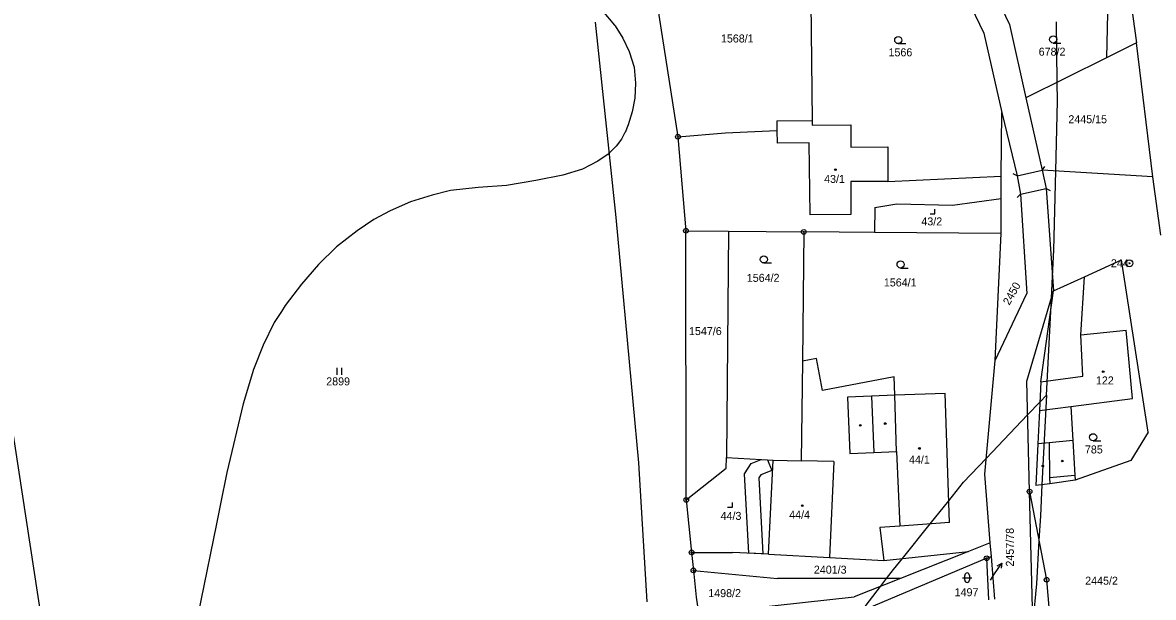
# Model space of a CAD drawing. Extents: x -546762 to -540209, y -1046851 to -1035694.
# Drawn here: x -542845.1 to -542604.8, y -1039792.3 to -1039670.1 of the extents above; entities that cross this region are included whole.
import ezdxf

# ---------------------------------------------------------------- set-up
doc = ezdxf.new("R2010")
doc.units = 0
for name, color, linetype in [('Vrstva 1', 7, 'Continuous'), ('Vrstva 16', 7, 'Continuous'), ('Vrstva 17', 7, 'Continuous'), ('Vrstva 18', 7, 'Continuous'), ('Vrstva 19', 7, 'Continuous'), ('Vrstva 24', 7, 'Continuous'), ('Vrstva 25', 7, 'Continuous'), ('Vrstva 26', 7, 'Continuous'), ('Vrstva 3', 7, 'Continuous'), ('Vrstva 30', 7, 'Continuous'), ('Vrstva 37', 7, 'Continuous'), ('Vrstva 4', 7, 'Continuous'), ('Vrstva 52', 7, 'Continuous')]:
    doc.layers.add(name, color=color, linetype=linetype)

msp = doc.modelspace()

# ---------------------------------------------------------------- linework, layer by layer
at = {"layer": 'Vrstva 1'}
for p, q in [((-542705.86, -1039694.34), (-542695.7, -1039693.46)), ((-542695.1, -1039714.41), (-542679.1, -1039714.55)), ((-542679.1, -1039714.55), (-542679.4, -1039742.03)), ((-542664.09, -1039714.68), (-542679.1, -1039714.55)), ((-542676.41, -1039741.47), (-542679.4, -1039742.03)), ((-542679.4, -1039742.03), (-542679.64, -1039763.24)), ((-542631.14, -1039769.78), (-542631.73, -1039746.29)), ((-542695.54, -1039762.52), (-542685.64, -1039763.13)), ((-542686.57, -1039783.12), (-542685.64, -1039763.13)), ((-542685.64, -1039763.13), (-542679.64, -1039763.24)), ((-542672.75, -1039763.36), (-542679.64, -1039763.24)), ((-542672.75, -1039763.36), (-542673.67, -1039783.8)), ((-542704.09, -1039771.57), (-542695.56, -1039764.83)), ((-542630.45, -1039797.36), (-542631.14, -1039769.78)), ((-542631.14, -1039769.78), (-542627.51, -1039788.55)), ((-542702.94, -1039782.71), (-542694.24, -1039782.72)), ((-542640.24, -1039783.98), (-542668.91, -1039796.07)), ((-542640.24, -1039783.98), (-542639.24, -1039783.56)), ((-542639.75, -1039792.83), (-542640.24, -1039783.98)), ((-542702.54, -1039786.55), (-542684.72, -1039788.3)), ((-542627.51, -1039788.55), (-542625.49, -1039812.67))]:
    msp.add_line(p, q, dxfattribs=at)
for points in [[(-542712.36, -1039652.51), (-542705.86, -1039694.34)], [(-542677.71, -1039653), (-542677.33, -1039690.89)], [(-542611.68, -1039650.85), (-542608.44, -1039674.34)], [(-542649.92, -1039653.39), (-542640.84, -1039672.31)], [(-542614.29, -1039655.34), (-542614.78, -1039677.52)], [(-542640.62, -1039659.5), (-542635.36, -1039670.45)], [(-542860.51, -1039670.07), (-542839.48, -1039807.43)], [(-542723.46, -1039669.94), (-542719.06, -1039711.53)], [(-542635.36, -1039670.45), (-542631.89, -1039686.08)], [(-542640.84, -1039672.31), (-542636.99, -1039689.14)], [(-542608.44, -1039674.34), (-542614.78, -1039677.52)], [(-542604.91, -1039702.82), (-542608.44, -1039674.34)], [(-542614.78, -1039677.52), (-542631.89, -1039686.08)], [(-542631.89, -1039686.08), (-542628.47, -1039701.44)], [(-542684.83, -1039690.96), (-542677.33, -1039690.89)], [(-542684.83, -1039690.96), (-542684.81, -1039693)], [(-542677.33, -1039690.89), (-542677.32, -1039691.89)], [(-542637.19, -1039702.74), (-542636.99, -1039689.14)], [(-542636.99, -1039689.14), (-542633.76, -1039702.65)], [(-542695.7, -1039693.46), (-542684.81, -1039693)], [(-542677.32, -1039691.89), (-542669.12, -1039691.81)], [(-542669.12, -1039691.81), (-542669.11, -1039696.52)], [(-542705.86, -1039694.34), (-542704.14, -1039714.33)], [(-542669.11, -1039696.52), (-542661.24, -1039696.5)], [(-542661.24, -1039696.5), (-542661.22, -1039703.84)], [(-542661.22, -1039703.84), (-542637.19, -1039702.74)], [(-542637.19, -1039707.46), (-542637.19, -1039702.74)], [(-542633.76, -1039702.65), (-542633.08, -1039706.56)], [(-542604.91, -1039702.82), (-542628.47, -1039701.44)], [(-542628.47, -1039701.44), (-542627.6, -1039705.31)], [(-542603.22, -1039715.27), (-542604.91, -1039702.82)], [(-542627.6, -1039705.31), (-542626.02, -1039727.12)], [(-542647.51, -1039708.9), (-542637.19, -1039707.46)], [(-542637.19, -1039714.92), (-542637.19, -1039707.46)], [(-542633.08, -1039706.56), (-542631.68, -1039727.64)], [(-542663.99, -1039709.39), (-542664.09, -1039714.68)], [(-542663.99, -1039709.39), (-542659.3, -1039708.58)], [(-542659.3, -1039708.58), (-542647.51, -1039708.9)], [(-542719.06, -1039711.53), (-542714.22, -1039763.64)], [(-542704.14, -1039714.33), (-542695.1, -1039714.41)], [(-542704.09, -1039771.57), (-542704.14, -1039714.33)], [(-542695.1, -1039714.41), (-542695.54, -1039762.52)], [(-542637.19, -1039714.92), (-542664.09, -1039714.68)], [(-542638.46, -1039741.92), (-542637.19, -1039714.92)], [(-542619.45, -1039724.1), (-542611.58, -1039720.48)], [(-542605.96, -1039757.18), (-542611.58, -1039720.48)], [(-542626.02, -1039727.12), (-542619.45, -1039724.1)], [(-542620.2, -1039736.44), (-542619.45, -1039724.1)], [(-542631.73, -1039746.29), (-542626.02, -1039727.12)], [(-542628.7, -1039746.43), (-542626.02, -1039727.12)], [(-542638.46, -1039741.92), (-542631.68, -1039727.64)], [(-542620.2, -1039736.44), (-542610.58, -1039735.47)], [(-542609.28, -1039750.02), (-542610.58, -1039735.47)], [(-542675.14, -1039748.26), (-542676.41, -1039741.47)], [(-542640.66, -1039766.08), (-542638.46, -1039741.92)], [(-542659.91, -1039745.41), (-542675.14, -1039748.26)], [(-542659.79, -1039749.31), (-542659.91, -1039745.41)], [(-542628.7, -1039746.43), (-542629, -1039752.54)], [(-542649.04, -1039748.96), (-542659.79, -1039749.31)], [(-542648.14, -1039776.38), (-542649.04, -1039748.96)], [(-542622.35, -1039751.69), (-542609.28, -1039750.02)], [(-542629, -1039752.54), (-542629.34, -1039759.61)], [(-542622.35, -1039751.69), (-542621.93, -1039758.95)], [(-542605.96, -1039757.18), (-542609.6, -1039763.17)], [(-542629.34, -1039759.61), (-542629.77, -1039768.52)], [(-542621.93, -1039758.95), (-542621.49, -1039766.28)], [(-542695.56, -1039764.83), (-542695.54, -1039762.52)], [(-542609.6, -1039763.17), (-542621.43, -1039767.35)], [(-542714.22, -1039763.64), (-542712.47, -1039793.24)], [(-542639.48, -1039780.67), (-542640.66, -1039766.08)], [(-542626.84, -1039768.11), (-542629.77, -1039768.52)], [(-542621.43, -1039767.35), (-542626.84, -1039768.11)], [(-542621.49, -1039766.28), (-542621.43, -1039767.35)], [(-542704.09, -1039771.57), (-542702.94, -1039782.71)], [(-542658.7, -1039777.12), (-542662.97, -1039777.42)], [(-542662.97, -1039777.42), (-542662.11, -1039784.41)], [(-542648.14, -1039776.38), (-542658.7, -1039777.12)], [(-542702.94, -1039782.71), (-542702.54, -1039786.55)], [(-542686.57, -1039783.12), (-542694.24, -1039782.72)], [(-542662.11, -1039784.41), (-542644.12, -1039782.52)], [(-542644.12, -1039782.52), (-542658.53, -1039788.26)], [(-542639.48, -1039780.67), (-542644.12, -1039782.52)], [(-542639.24, -1039783.56), (-542639.48, -1039780.67)], [(-542686.57, -1039783.12), (-542673.67, -1039783.8)], [(-542673.67, -1039783.8), (-542662.11, -1039784.41)], [(-542638.5, -1039792.69), (-542639.24, -1039783.56)], [(-542702.54, -1039786.55), (-542701.96, -1039792.23)], [(-542658.53, -1039788.26), (-542684.72, -1039788.3)], [(-542658.53, -1039788.26), (-542668.4, -1039792.2)], [(-542701.96, -1039792.23), (-542700.85, -1039799.89)], [(-542690.32, -1039794.61), (-542668.4, -1039792.2)]]:
    msp.add_lwpolyline(points, dxfattribs=at)
at = {"layer": 'Vrstva 16'}
msp.add_line((-542638.69, -1039787.5), (-542637.04, -1039784.99), dxfattribs=at)
for points in [[(-542638.01, -1039785.55), (-542637.04, -1039784.99), (-542637.17, -1039786.1)], [(-542639.43, -1039788.63), (-542638.69, -1039787.5)]]:
    msp.add_lwpolyline(points, dxfattribs=at)
at = {"layer": 'Vrstva 24'}
for centre, radius in [((-542705.86, -1039694.34), 0.5), ((-542705.86, -1039694.34), 0.1), ((-542704.14, -1039714.33), 0.5), ((-542704.14, -1039714.33), 0.1), ((-542679.1, -1039714.55), 0.5), ((-542679.1, -1039714.55), 0.1), ((-542609.92, -1039721.23), 0.75), ((-542609.92, -1039721.23), 0.1), ((-542631.14, -1039769.78), 0.5), ((-542631.14, -1039769.78), 0.1), ((-542704.09, -1039771.57), 0.5), ((-542704.09, -1039771.57), 0.1), ((-542702.94, -1039782.71), 0.5), ((-542702.94, -1039782.71), 0.1), ((-542640.24, -1039783.98), 0.5), ((-542640.24, -1039783.98), 0.1), ((-542702.54, -1039786.55), 0.5), ((-542702.54, -1039786.55), 0.1), ((-542627.51, -1039788.55), 0.5), ((-542627.51, -1039788.55), 0.1)]:
    msp.add_circle(centre, radius, dxfattribs=at)
at = {"layer": 'Vrstva 25'}
for p, q in [((-542659.03, -1039674.52), (-542657.43, -1039674.52)), ((-542626.11, -1039674.39), (-542624.51, -1039674.39)), ((-542687.59, -1039721.17), (-542685.99, -1039721.17)), ((-542658.54, -1039722.24), (-542656.94, -1039722.24)), ((-542778.25, -1039744.99), (-542778.25, -1039743.49)), ((-542777.25, -1039744.99), (-542777.25, -1039743.49)), ((-542617.62, -1039758.98), (-542616.02, -1039758.98)), ((-542644.9, -1039788.6), (-542644.9, -1039787.6)), ((-542643.9, -1039787.6), (-542643.9, -1039788.6)), ((-542645.4, -1039788.1), (-542643.4, -1039788.1))]:
    msp.add_line(p, q, dxfattribs=at)
for points in [[(-542652.28, -1039710.75), (-542651.28, -1039710.75), (-542651.28, -1039709.75)], [(-542695.28, -1039773.11), (-542694.28, -1039773.11), (-542694.28, -1039772.11)]]:
    msp.add_lwpolyline(points, dxfattribs=at)
for centre, radius in [((-542659.03, -1039673.77), 0.75), ((-542626.11, -1039673.64), 0.75), ((-542672.37, -1039701.34), 0.175), ((-542687.59, -1039720.42), 0.75), ((-542658.54, -1039721.49), 0.75), ((-542615.48, -1039744.3), 0.175), ((-542667.1, -1039755.71), 0.175), ((-542661.8, -1039755.32), 0.175), ((-542617.62, -1039758.23), 0.75), ((-542654.53, -1039760.62), 0.175), ((-542624.17, -1039763.3), 0.175), ((-542628.31, -1039764.34), 0.175), ((-542679.42, -1039772.77), 0.175)]:
    msp.add_circle(centre, radius, dxfattribs=at)
for centre, start, end in [((-542644.4, -1039787.6), 0, 180), ((-542644.4, -1039788.6), 180, 0)]:
    msp.add_arc(centre, 0.5, start, end, dxfattribs=at)
at = {"layer": 'Vrstva 26'}
for p, q in [((-542628.47, -1039701.44), (-542627.86, -1039700.65)), ((-542633.76, -1039702.65), (-542634.64, -1039702.18)), ((-542627.6, -1039705.31), (-542626.73, -1039705.79)), ((-542633.08, -1039706.56), (-542633.79, -1039707.27))]:
    msp.add_line(p, q, dxfattribs=at)
at = {"layer": 'Vrstva 3'}
for points in [[(-542684.83, -1039690.96), (-542677.33, -1039690.89)], [(-542684.83, -1039690.96), (-542684.81, -1039693)], [(-542677.33, -1039690.89), (-542677.32, -1039691.89)], [(-542684.81, -1039693), (-542684.78, -1039695.71)], [(-542677.32, -1039691.89), (-542669.12, -1039691.81)], [(-542669.12, -1039691.81), (-542669.11, -1039696.52)], [(-542677.93, -1039695.65), (-542684.78, -1039695.71)], [(-542677.78, -1039710.95), (-542677.93, -1039695.65)], [(-542669.11, -1039696.52), (-542661.24, -1039696.5)], [(-542661.24, -1039696.5), (-542661.22, -1039703.84)], [(-542661.22, -1039703.84), (-542669.09, -1039703.86)], [(-542669.09, -1039703.86), (-542669.08, -1039710.86)], [(-542669.08, -1039710.86), (-542677.78, -1039710.95)], [(-542620.2, -1039736.44), (-542610.58, -1039735.47)], [(-542619.81, -1039745.22), (-542620.2, -1039736.44)], [(-542609.28, -1039750.02), (-542610.58, -1039735.47)], [(-542628.7, -1039746.43), (-542629, -1039752.54)], [(-542628.7, -1039746.43), (-542619.81, -1039745.22)], [(-542649.04, -1039748.96), (-542659.79, -1039749.31)], [(-542648.14, -1039776.38), (-542649.04, -1039748.96)], [(-542659.4, -1039761.29), (-542659.79, -1039749.31)], [(-542622.35, -1039751.69), (-542609.28, -1039750.02)], [(-542629, -1039752.54), (-542622.35, -1039751.69)], [(-542686.57, -1039783.12), (-542685.64, -1039763.13)], [(-542685.64, -1039763.13), (-542679.64, -1039763.24)], [(-542672.75, -1039763.36), (-542679.64, -1039763.24)], [(-542672.75, -1039763.36), (-542673.67, -1039783.8)], [(-542659.4, -1039761.29), (-542658.7, -1039777.12)], [(-542648.14, -1039776.38), (-542658.7, -1039777.12)], [(-542686.57, -1039783.12), (-542673.67, -1039783.8)]]:
    msp.add_lwpolyline(points, dxfattribs=at)
at = {"layer": 'Vrstva 30'}
for points in [[(-542690.25, -1039763.84), (-542688.14, -1039762.98), (-542686.82, -1039763.06), (-542685.9, -1039765.3)], [(-542691.69, -1039766.02), (-542690.25, -1039763.84)], [(-542685.9, -1039765.3), (-542688.25, -1039766.26), (-542688.65, -1039766.86), (-542687.8, -1039783.06), (-542690.81, -1039782.9), (-542691.69, -1039766.02)]]:
    msp.add_lwpolyline(points, dxfattribs=at)
at = {"layer": 'Vrstva 37'}
for centre in [(-542672.37, -1039701.34), (-542615.48, -1039744.3), (-542654.53, -1039760.62), (-542679.42, -1039772.77)]:
    msp.add_circle(centre, 0.175, dxfattribs=at)
at = {"layer": 'Vrstva 4'}
for points in [[(-542684.81, -1039693), (-542684.78, -1039695.71)], [(-542677.93, -1039695.65), (-542684.78, -1039695.71)], [(-542677.78, -1039710.95), (-542677.93, -1039695.65)], [(-542633.76, -1039702.65), (-542628.47, -1039701.44)], [(-542661.22, -1039703.84), (-542669.09, -1039703.86)], [(-542669.09, -1039703.86), (-542669.08, -1039710.86)], [(-542633.08, -1039706.56), (-542627.6, -1039705.31)], [(-542669.08, -1039710.86), (-542677.78, -1039710.95)], [(-542619.81, -1039745.22), (-542620.2, -1039736.44)], [(-542628.7, -1039746.43), (-542619.81, -1039745.22)], [(-542664.69, -1039749.51), (-542669.78, -1039749.72)], [(-542669.78, -1039749.72), (-542669.29, -1039761.66)], [(-542659.79, -1039749.31), (-542664.69, -1039749.51)], [(-542664.69, -1039749.51), (-542664.24, -1039761.47)], [(-542659.4, -1039761.29), (-542659.79, -1039749.31)], [(-542629, -1039752.54), (-542622.35, -1039751.69)], [(-542626.94, -1039759.4), (-542629.34, -1039759.61)], [(-542621.93, -1039758.95), (-542626.94, -1039759.4)], [(-542626.94, -1039759.4), (-542626.86, -1039766.76)], [(-542669.29, -1039761.66), (-542664.24, -1039761.47)], [(-542664.24, -1039761.47), (-542659.4, -1039761.29)], [(-542659.4, -1039761.29), (-542658.7, -1039777.12)], [(-542626.86, -1039766.76), (-542621.49, -1039766.28)], [(-542626.86, -1039766.76), (-542626.84, -1039768.11)]]:
    msp.add_lwpolyline(points, dxfattribs=at)
at = {"layer": 'Vrstva 52'}
for points in [[(-542721.94, -1039667.45), (-542719.31, -1039670.58), (-542719.19, -1039670.77), (-542717.55, -1039673.36), (-542716.19, -1039676.19), (-542715.11, -1039679.51), (-542714.87, -1039682.92), (-542715.02, -1039686.1), (-542715.55, -1039689.02), (-542716.43, -1039691.8), (-542717.08, -1039693.44), (-542717.17, -1039693.6), (-542717.81, -1039694.81), (-542718.93, -1039696.32), (-542720.52, -1039697.86), (-542720.69, -1039698.03), (-542722.89, -1039699.49), (-542726.1, -1039701.2), (-542730.3, -1039702.52), (-542736.01, -1039703.64), (-542742.25, -1039704.67), (-542748.32, -1039705.1), (-542754.13, -1039705.79), (-542758.05, -1039706.72), (-542762.66, -1039708.18), (-542767.02, -1039710.06), (-542770.43, -1039711.93), (-542774.02, -1039714.33), (-542778.37, -1039717.74), (-542782.21, -1039721.5), (-542785.79, -1039725.68), (-542789.29, -1039730.21), (-542790.1, -1039731.47)], [(-542627.53, -1039749.28), (-542626.62, -1039731.47), (-542626.48, -1039728.66), (-542626.24, -1039724.02), (-542625.96, -1039718.42), (-542625.55, -1039701.61), (-542625.18, -1039686.78), (-542625.24, -1039682.75), (-542625.43, -1039669.9)], [(-542790.1, -1039731.47), (-542791.6, -1039733.8), (-542793.99, -1039738.66), (-542796.01, -1039743.79), (-542798.25, -1039751.11), (-542801.69, -1039765.76), (-542803.05, -1039772.42), (-542803.9, -1039776.63), (-542807.22, -1039792.94), (-542807.74, -1039795.48), (-542807.96, -1039796.54), (-542815.66, -1039838.18), (-542818.36, -1039852.76)], [(-542799.7, -1039922.92), (-542766.24, -1039893.88), (-542718.4, -1039851.52), (-542716.86, -1039850.04), (-542705.95, -1039839.57), (-542701.66, -1039835.46), (-542696.42, -1039830.43), (-542692.73, -1039826.9), (-542688.04, -1039821.34), (-542674.17, -1039804.93), (-542667.3, -1039795.89), (-542666.74, -1039795.15), (-542662.79, -1039789.96), (-542661.5, -1039788.26), (-542660.05, -1039786.36), (-542658.15, -1039783.99), (-542652.27, -1039776.67), (-542648.29, -1039771.72), (-542645.15, -1039767.8), (-542640.36, -1039762.76), (-542631.55, -1039753.5), (-542628.91, -1039750.73), (-542627.53, -1039749.28)], [(-542627.53, -1039749.28), (-542628.5, -1039768.34), (-542628.84, -1039774.91), (-542629.13, -1039780.17), (-542629.64, -1039789.41), (-542630.43, -1039797.49)]]:
    msp.add_lwpolyline(points, dxfattribs=at)

# ---------------------------------------------------------------- texts
at = {"layer": 'Vrstva 16'}
msp.add_text('2457/78', height=1.7, rotation=90, dxfattribs=at).set_placement((-542634.47, -1039785.73))
at = {"layer": 'Vrstva 17'}
msp.add_text('244', height=1.7, dxfattribs=at).set_placement((-542613.85, -1039722.08))
at = {"layer": 'Vrstva 18'}
for s, height, p in [('1568/1', 1.7, (-542696.71, -1039674.28)), ('1566', 1.7, (-542661.1, -1039677.22)), ('678/2', 1.7, (-542629.19, -1039677.09)), ('2445/15', 1.7, (-542622.89, -1039691.45)), ('1564/2', 1.7, (-542691.21, -1039725.18)), ('1564/1', 1.7, (-542662.09, -1039726.16)), ('1547/6', 1.7, (-542703.49, -1039736.5)), ('2899', 1.7, (-542780.57, -1039747.2)), ('785', 1.7, (-542619.37, -1039761.68)), ('2401/3', 1.7, (-542676.96, -1039787.25)), ('2457/78', 0.1, (-542639.43, -1039788.63)), ('2445/2', 1.7, (-542619.31, -1039789.59)), ('1498/2', 1.7, (-542699.4, -1039792.23)), ('1497', 1.7, (-542647.05, -1039792.04))]:
    msp.add_text(s, height=height, dxfattribs=at).set_placement(p)
msp.add_text('2450', height=1.7, rotation=60.8128, dxfattribs=at).set_placement((-542635.42, -1039730.28))
at = {"layer": 'Vrstva 19'}
for s, p in [('43/1', (-542674.78, -1039704.15)), ('43/2', (-542654.12, -1039713.18)), ('122', (-542617.03, -1039747)), ('44/1', (-542656.75, -1039763.84)), ('44/3', (-542696.78, -1039775.81)), ('44/4', (-542682.2, -1039775.56))]:
    msp.add_text(s, height=1.7, dxfattribs=at).set_placement(p)

doc.saveas('drawing.dxf')
